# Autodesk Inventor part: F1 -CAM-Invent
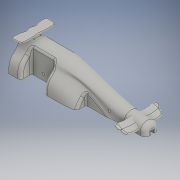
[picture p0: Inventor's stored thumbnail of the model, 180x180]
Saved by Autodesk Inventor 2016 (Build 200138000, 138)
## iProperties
Created: 2016-01
Part Number: F1 -CAM-Invent
Material: Generic
Document SubType Name: Modeling
Designer: PhillipD
Density: 1 g/cm^3
Appearance: Default
Author: PhillipD
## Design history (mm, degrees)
sketch "Sketch1"
  geometry: L1 (0, 0)-(65, 0); L2 (65, 0)-(65, -210); L3 (65, -210)-(0, -210); L4 (0, -210)-(0, 0)
  constraints: 8 end point, 2 parallel, 1 horizontal, 1 perpendicular
  dimensions: "d0" = 65 distance of L2.end L3.end; "d1" = 210 distance of L1.end L2.end
extrude "Extrusion1" new body sketch "Sketch1" distance "d2" = 50; taper "d3" = 0 deg
sketch "Sketch3"
  geometry: L1 (65, 0)-(0, 0) reference; L2 (65, 0)-(65, 50) reference; C1 r 9.5 at (32.5, 29)
  constraints: 1 centre point
  dimensions: "d4" = 19 diameter of C1; "d5" = 29 distance from line of L1 C1.centre; "d6" = 32.5 distance from line of L2 C1.centre
extrude "Extrusion2" cut sketch "Sketch3" distance "d7" = 52; taper "d8" = 0 deg
sketch "Sketch4"
  geometry: L1 (29.5, 6)-(35.5, 6); L2 (35.5, 6)-(35.5, 0); L3 (35.5, 0)-(29.5, 0); L4 (29.5, 0)-(29.5, 6); L5 (65, 0)-(0, 0) reference; 2 further points
  constraints: 8 end point, 2 midpoint, 2 parallel, 1 collinear, 1 horizontal, 1 perpendicular, 1 vertical alignment
  dimensions: "d9" = 6 distance of L2.end L3.end; "d10" = 6 distance of L1.end L2.end
extrude "Extrusion3" cut sketch "Sketch4" stored distance "d11" = 52; taper "d12" = 0 deg
sketch "Sketch5"
  geometry: L1 (210, 0)-(0, 0) reference; L2 (0, 0)-(0, 50) reference; L3 (210, 0)-(210, 50) reference; 2 further points
  dimensions: "d13" = 10 distance from line of L1 point (40, 10); "d14" = 40 distance from line of point (40, 10) L2; "d15" = 10 distance from line of L1 point (150, 10); "d16" = 60 distance from line of point (150, 10) L3
hole "Hole1" sketch "Sketch5" at (40, 10), (150, 10) diameter "d17" = 4; stored, may be unused: countersink angle "d21" = 90 deg, drill point angle "d23" = 118 deg; dims "d18" = 6, "d19" = 4, "d20" = 2, "d22" = 8
sketch "Sketch6"
  geometry: L1 (0, 190)-(-19, 190); L2 (-19, 190)-(-19, 150); L3 (-19, 150)-(0, 150); L4 (0, 150)-(0, 190); L5 (0, 0)-(-19, 0); L6 (-19, 0)-(-19, 98); L7 (-19, 98)-(0, 98); L8 (0, 98)-(0, 0); L9 (0, 210)-(-65, 210) reference
  constraints: 16 end point, 4 parallel, 2 horizontal, 2 perpendicular
  dimensions: "d24" = 19 distance of L3.end L2.end; "d25" = 40 distance of L2.end L1.end; "d26" = 19 distance of L6.end L7.end; "d27" = 98 distance of L5.end L6.end; "d28" = 20 distance between parallel lines of L9 L1
extrude "Extrusion4" cut sketch "Sketch6" stored distance "d29" = 10; taper "d30" = 0 deg
workplane "Work Plane1"
mirror "Mirror1"
sketch "Sketch7"
  geometry: L1 (0, 210)-(-65, 210) reference; 3 further points
  constraints: 1 midpoint, 1 vertical alignment
  dimensions: "d31" = 105 distance from line of point (-32.5, 105) L1
feature "Form1"
split "Split1"
sketch "Sketch8"
  geometry: L1 (20, 0)-(0, 0) reference; 3 further points
  constraints: 1 midpoint, 1 vertical alignment
  dimensions: "d32" = 51 distance from line of L1 point (10, 51)
feature "Form2"
feature "Form3"
workplane "Work Plane2"
sketch "Sketch9"
  geometry: L1 (-4, 6)-(4, 6); L2 (4, 6)-(4, 14); L3 (4, 14)-(-4, 14); L4 (-4, 14)-(-4, 6); L5 (-3, 0)-(3, 0) reference; L6 (32.5, 20)-(32.5, 0) reference; 5 further points
  constraints: 8 end point, 4 midpoint, 2 parallel, 1 horizontal, 1 horizontal alignment, 1 perpendicular, 1 vertical alignment
  dimensions: "d33" = 8 distance of L3.end L2.end; "d34" = 8 distance of L2.end L1.end
extrude "Extrusion5" new body sketch "Sketch9" distance "d35" = 5; taper "d37" = 0 deg; dims "d36" = 3, "d38" = 0
combine "Combine5"
combine "Combine6"
  body "Solid4"
workplane "Work Plane7"
split "Split2"
  body "Solid1"
sketch "Sketch11"
  geometry: L1 (-2, 7)-(8, 7); L2 (8, 7)-(8, 3); L3 (8, 3)-(-2, 3); L4 (-2, 3)-(-2, 7); L5 (14.966, -6)-(6, -6) reference; L6 (6, 0)-(0, 0) reference; 3 further points
  constraints: 8 end point, 2 midpoint, 2 parallel, 1 horizontal, 1 perpendicular, 1 vertical alignment
  dimensions: "d47" = 10 distance of L2.end L3.end; "d48" = 4 distance of L1.end L2.end; "d49" = 13 distance between parallel lines of L5 L1
extrude "Extrusion7" join sketch "Sketch11" distance "d50" = 10; taper "d51" = 0 deg
combine "Combine7"
fillet "Fillet1" dims "d52" = 3
fillet "Fillet2" dims "d53" = 5
fillet "Fillet3" dims "d54" = 8
fillet "Fillet4" dims "d55" = 3
body "Srf1"
body "Solid2"
body "Solid3"
body "Solid6"
body "Solid7"
other parameters: "d46" = -35
